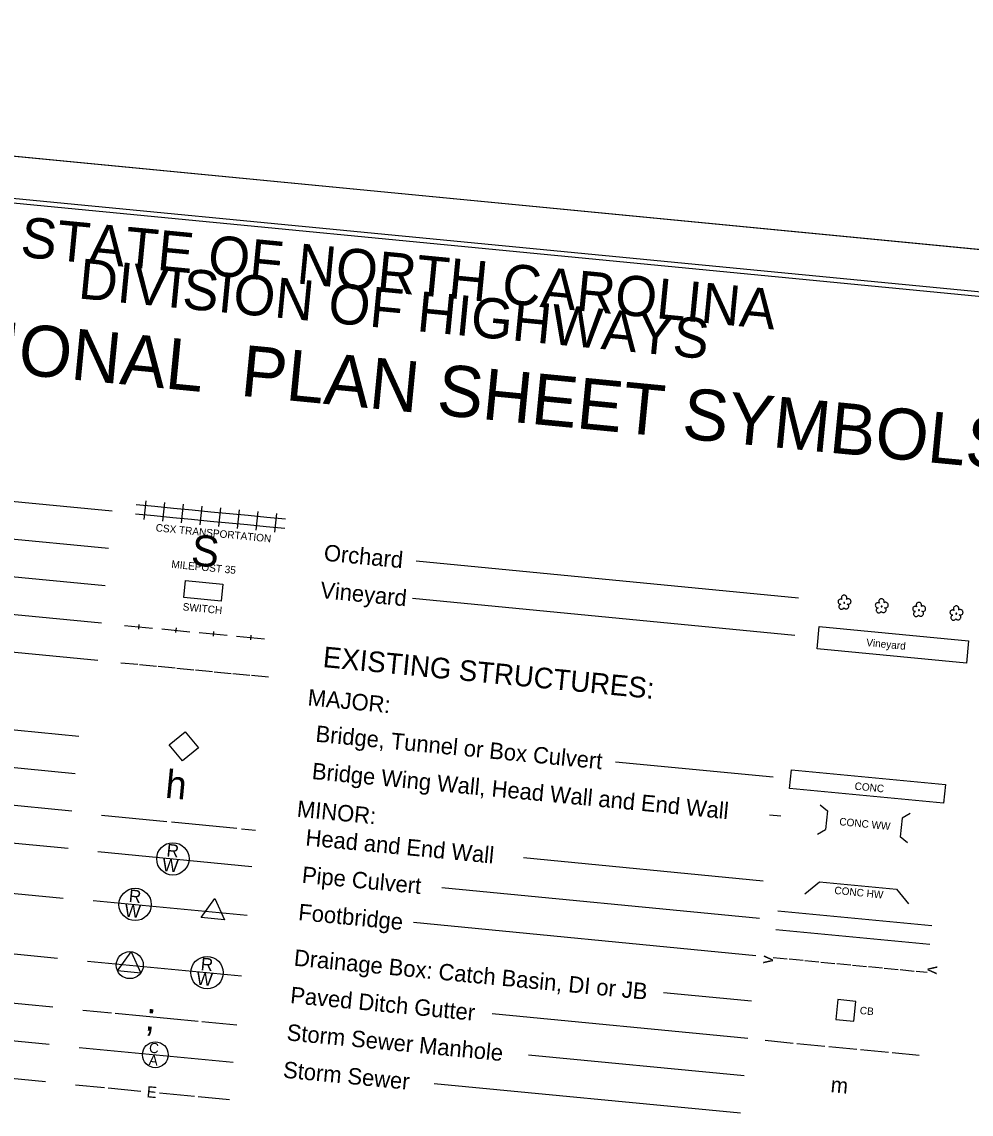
# Model space of a CAD drawing. Extents: x 2060574 to 2063008, y 912203 to 913082.
# Drawn here: x 2062450.1 to 2062753.8, y 912607.4 to 912956.9 of the extents above; entities that cross this region are included whole.
import ezdxf

# ---------------------------------------------------------------- set-up
doc = ezdxf.new("R2010")
doc.units = 0
for name, color, linetype in [('Sheet Cutting Line CELL', 7, 'Continuous'), ('Sheet Data Field CELL', 7, 'Continuous'), ('Sheet Plot Border Inside CELL', 7, 'Continuous'), ('Sheet Plot Border Outside CELL', 7, 'Continuous'), ('Sheet Symbology CELL', 7, 'Continuous')]:
    doc.layers.add(name, color=color, linetype=linetype)

msp = doc.modelspace()

# ---------------------------------------------------------------- linework, layer by layer
at = {"layer": 'Sheet Cutting Line CELL'}
msp.add_line((2063008.23, 912859.64), (2062002.51, 912956.86), dxfattribs=at)
at = {"layer": 'Sheet Data Field CELL'}
msp.add_lwpolyline([(2062497.24, 912725.52), (2062502.37, 912729.74), (2062506.59, 912724.62), (2062501.46, 912720.39)], close=True, dxfattribs=at)
at = {"layer": 'Sheet Plot Border Inside CELL'}
msp.add_lwpolyline([(2061948.07, 912312.58), (2062943.33, 912216.37), (2063004.24, 912846.49), (2062008.98, 912942.7)], close=True, dxfattribs=at)
at = {"layer": 'Sheet Plot Border Outside CELL'}
msp.add_lwpolyline([(2061939.01, 912299.92), (2062944.72, 912202.7), (2063008.23, 912859.64), (2062002.51, 912956.86)], close=True, dxfattribs=at)
at = {"layer": 'Sheet Symbology CELL'}
for p, q in [((2062479.03, 912800.31), (2062384.42, 912809.46)), ((2062486.7, 912802.44), (2062492.67, 912801.86)), ((2062489.26, 912797.67), (2062489.83, 912803.65)), ((2062495.23, 912797.1), (2062495.8, 912803.07)), ((2062501.2, 912796.52), (2062501.78, 912802.49)), ((2062486.41, 912799.45), (2062492.39, 912798.88)), ((2062492.39, 912798.88), (2062498.36, 912798.3)), ((2062492.67, 912801.86), (2062498.65, 912801.29)), ((2062498.65, 912801.29), (2062504.62, 912800.71)), ((2062504.62, 912800.71), (2062510.59, 912800.13)), ((2062507.17, 912795.94), (2062507.75, 912801.91)), ((2062510.59, 912800.13), (2062516.56, 912799.55)), ((2062513.14, 912795.36), (2062513.72, 912801.34)), ((2062516.56, 912799.55), (2062522.54, 912798.98)), ((2062519.12, 912794.79), (2062519.69, 912800.76)), ((2062522.54, 912798.98), (2062528.51, 912798.4)), ((2062525.09, 912794.21), (2062525.67, 912800.18)), ((2062531.06, 912793.63), (2062531.64, 912799.6)), ((2062477.87, 912788.37), (2062388.56, 912797)), ((2062498.36, 912798.3), (2062504.33, 912797.72)), ((2062504.33, 912797.72), (2062510.3, 912797.15)), ((2062510.3, 912797.15), (2062516.27, 912796.57)), ((2062516.27, 912796.57), (2062522.25, 912795.99)), ((2062522.25, 912795.99), (2062528.22, 912795.41)), ((2062528.22, 912795.41), (2062534.19, 912794.84)), ((2062528.51, 912798.4), (2062534.48, 912797.82)), ((2062476.72, 912776.42), (2062348.37, 912788.83)), ((2062698.6, 912772.5), (2062576.21, 912784.33)), ((2062475.56, 912764.48), (2062376.33, 912774.07)), ((2062697.45, 912760.55), (2062575.06, 912772.38)), ((2062482.96, 912763.76), (2062491.92, 912762.9)), ((2062487.51, 912764.08), (2062487.37, 912762.58)), ((2062474.41, 912752.53), (2062375.17, 912762.13)), ((2062474.41, 912752.53), (2062375.17, 912762.13)), ((2062494.91, 912762.61), (2062503.87, 912761.74)), ((2062499.46, 912762.92), (2062499.31, 912761.43)), ((2062506.85, 912761.45), (2062515.81, 912760.59)), ((2062511.4, 912761.77), (2062511.26, 912760.28)), ((2062518.8, 912760.3), (2062527.75, 912759.43)), ((2062523.35, 912760.61), (2062523.2, 912759.12)), ((2062481.81, 912751.82), (2062487.18, 912751.3)), ((2062487.78, 912751.24), (2062493.16, 912750.72)), ((2062493.75, 912750.66), (2062499.13, 912750.15)), ((2062499.73, 912750.09), (2062505.1, 912749.57)), ((2062505.7, 912749.51), (2062511.07, 912748.99)), ((2062511.67, 912748.93), (2062517.04, 912748.41)), ((2062517.64, 912748.36), (2062523.02, 912747.84)), ((2062523.61, 912747.78), (2062528.99, 912747.26)), ((2062468.36, 912728.19), (2062400.15, 912734.79)), ((2062467.2, 912716.25), (2062416.47, 912721.15)), ((2062690.46, 912715.14), (2062640.04, 912720.01)), ((2062466.05, 912704.31), (2062415.32, 912709.21)), ((2062705.55, 912706.36), (2062707.84, 912704.42)), ((2062707.84, 912704.42), (2062707.26, 912698.44)), ((2062475.59, 912703.04), (2062496.49, 912701.02)), ((2062497.98, 912700.87), (2062518.88, 912698.85)), ((2062689.3, 912703.19), (2062692.88, 912702.85)), ((2062731.72, 912702.11), (2062731.15, 912696.13)), ((2062734.34, 912703.58), (2062731.72, 912702.11)), ((2062520.38, 912698.71), (2062524.86, 912698.27)), ((2062704.64, 912696.97), (2062707.26, 912698.44)), ((2062464.89, 912692.36), (2062414.17, 912697.26)), ((2062733.43, 912694.19), (2062731.15, 912696.13)), ((2062474.46, 912691.36), (2062523.73, 912686.6)), ((2062687.25, 912681.95), (2062610.63, 912689.36)), ((2062463.34, 912676.33), (2062423.26, 912680.2)), ((2062700.63, 912677.9), (2062705.26, 912681.72)), ((2062705.26, 912681.72), (2062729.9, 912679.33)), ((2062686.09, 912670.01), (2062584.45, 912679.83)), ((2062729.9, 912679.33), (2062733.72, 912674.7)), ((2062472.95, 912675.76), (2062522.22, 912671)), ((2062511.44, 912672.04), (2062511.44, 912672.04)), ((2062691.94, 912672.46), (2062741.21, 912667.69)), ((2062684.94, 912658.06), (2062575.36, 912668.65)), ((2062691.36, 912666.48), (2062740.63, 912661.72)), ((2062461.49, 912657.19), (2062421.41, 912661.07)), ((2062471.07, 912656.35), (2062520.34, 912651.59)), ((2062690.49, 912657.52), (2062694.97, 912657.09)), ((2062695.57, 912657.03), (2062700.05, 912656.6)), ((2062700.65, 912656.54), (2062705.12, 912656.11)), ((2062705.72, 912656.05), (2062710.2, 912655.62)), ((2062710.8, 912655.56), (2062715.28, 912655.13)), ((2062484.63, 912655.04), (2062484.63, 912655.04)), ((2062715.87, 912655.07), (2062720.35, 912654.64)), ((2062720.95, 912654.58), (2062725.43, 912654.15)), ((2062726.03, 912654.09), (2062730.51, 912653.66)), ((2062731.1, 912653.6), (2062735.58, 912653.17)), ((2062736.18, 912653.11), (2062739.76, 912652.76)), ((2062459.98, 912641.6), (2062401.73, 912647.23)), ((2062683.53, 912643.47), (2062655.34, 912646.2)), ((2062469.56, 912640.67), (2062478.79, 912639.78)), ((2062479.99, 912639.66), (2062506.51, 912637.1)), ((2062682.37, 912631.53), (2062600.59, 912639.43)), ((2062458.83, 912629.65), (2062400.57, 912635.29)), ((2062507.71, 912636.99), (2062518.83, 912635.91)), ((2062687.93, 912630.99), (2062696.89, 912630.12)), ((2062468.4, 912628.73), (2062517.67, 912623.97)), ((2062698.08, 912630.01), (2062707.04, 912629.14)), ((2062708.23, 912629.03), (2062717.19, 912628.16)), ((2062718.39, 912628.05), (2062727.34, 912627.18)), ((2062681.22, 912619.58), (2062612.14, 912626.26)), ((2062728.54, 912627.06), (2062737.2, 912626.23)), ((2062457.68, 912617.71), (2062399.42, 912623.34)), ((2062680.06, 912607.64), (2062582, 912617.12)), ((2062467.25, 912616.78), (2062476.51, 912615.89)), ((2062477.71, 912615.77), (2062488.16, 912614.76)), ((2062494.13, 912614.19), (2062505.33, 912613.1)), ((2062506.52, 912612.99), (2062516.52, 912612.02))]:
    msp.add_line(p, q, dxfattribs=at)
for points in [[(2062996.63, 912845.69), (2062100.81, 912932.29), (2062040.25, 912305.82), (2062936.07, 912219.22)], [(2062502.44, 912778.13), (2062514.38, 912776.98), (2062513.86, 912771.55), (2062501.91, 912772.7)], [(2062507.5, 912670.25), (2062511.86, 912676.34), (2062514.97, 912669.53)], [(2062480.69, 912653.25), (2062485.05, 912659.34), (2062488.16, 912652.53)], [(2062710.54, 912637.66), (2062716.28, 912637.1), (2062716.89, 912643.46), (2062711.15, 912644.01)]]:
    msp.add_lwpolyline(points, close=True, dxfattribs=at)
for points in [[(2062713.9, 912772.07), (2062714, 912772.25), (2062714.05, 912772.42), (2062714.04, 912772.6), (2062714.03, 912772.79), (2062713.95, 912772.94), (2062713.88, 912773.1), (2062713.74, 912773.24), (2062713.6, 912773.34), (2062713.4, 912773.42), (2062713.25, 912773.43), (2062713.06, 912773.42), (2062712.88, 912773.38), (2062712.72, 912773.3), (2062712.56, 912773.2), (2062712.45, 912773.03), (2062712.38, 912772.88), (2062712.33, 912772.71), (2062712.31, 912772.53), (2062712.33, 912772.35), (2062712.4, 912772.19), (2062712.5, 912772), (2062712.36, 912772.1), (2062712.19, 912772.15), (2062712.01, 912772.17), (2062711.85, 912772.12), (2062711.7, 912772.08), (2062711.54, 912771.97), (2062711.41, 912771.86), (2062711.3, 912771.72), (2062711.26, 912771.58), (2062711.21, 912771.37), (2062711.22, 912771.22), (2062711.27, 912771.06), (2062711.37, 912770.9), (2062711.45, 912770.77), (2062711.59, 912770.67), (2062711.76, 912770.56), (2062711.91, 912770.52), (2062712.09, 912770.5), (2062711.93, 912770.46), (2062711.77, 912770.35), (2062711.67, 912770.24), (2062711.59, 912770.07), (2062711.52, 912769.89), (2062711.5, 912769.74), (2062711.52, 912769.56), (2062711.59, 912769.4), (2062711.67, 912769.25), (2062711.77, 912769.12), (2062711.91, 912769.01), (2062712.06, 912768.94), (2062712.24, 912768.92), (2062712.42, 912768.9), (2062712.57, 912768.92), (2062712.73, 912769.02), (2062712.89, 912769.1), (2062713.06, 912769.35)], [(2062713.06, 912769.35), (2062713.4, 912769.11), (2062713.57, 912769.03), (2062713.75, 912768.98), (2062713.93, 912769), (2062714.09, 912769.04), (2062714.25, 912769.12), (2062714.41, 912769.22), (2062714.51, 912769.36), (2062714.58, 912769.51), (2062714.66, 912769.68), (2062714.65, 912769.86), (2062714.64, 912770.04), (2062714.53, 912770.23), (2062714.46, 912770.36), (2062714.32, 912770.47), (2062714.14, 912770.57), (2062714.32, 912770.53), (2062714.53, 912770.51), (2062714.69, 912770.55), (2062714.87, 912770.62), (2062715.03, 912770.7), (2062715.16, 912770.84), (2062715.27, 912771.01), (2062715.32, 912771.18), (2062715.37, 912771.36), (2062715.35, 912771.54), (2062715.31, 912771.73), (2062715.21, 912771.89), (2062715.07, 912772.05), (2062714.93, 912772.16), (2062714.76, 912772.23), (2062714.58, 912772.28), (2062714.4, 912772.3), (2062714.22, 912772.25), (2062714.06, 912772.18), (2062713.9, 912772.07)], [(2062713.29, 912771.08), (2062713.2, 912771.09), (2062713.14, 912771.06), (2062713.07, 912771.04), (2062713.07, 912770.95), (2062713.06, 912770.89), (2062713.11, 912770.82), (2062713.2, 912770.82), (2062713.26, 912770.81), (2062713.33, 912770.86), (2062713.37, 912770.95), (2062713.34, 912771.01), (2062713.29, 912771.08)], [(2062725.84, 912770.92), (2062725.95, 912771.09), (2062726, 912771.27), (2062725.98, 912771.45), (2062725.97, 912771.63), (2062725.9, 912771.79), (2062725.82, 912771.95), (2062725.68, 912772.08), (2062725.54, 912772.18), (2062725.34, 912772.26), (2062725.19, 912772.28), (2062725.01, 912772.27), (2062724.82, 912772.22), (2062724.67, 912772.15), (2062724.5, 912772.04), (2062724.4, 912771.87), (2062724.32, 912771.73), (2062724.28, 912771.55), (2062724.26, 912771.37), (2062724.27, 912771.19), (2062724.35, 912771.03), (2062724.45, 912770.84), (2062724.31, 912770.95), (2062724.13, 912771), (2062723.95, 912771.01), (2062723.8, 912770.97), (2062723.64, 912770.92), (2062723.48, 912770.82), (2062723.35, 912770.71), (2062723.25, 912770.57), (2062723.2, 912770.42), (2062723.15, 912770.22), (2062723.17, 912770.06), (2062723.21, 912769.91), (2062723.32, 912769.75), (2062723.4, 912769.62), (2062723.54, 912769.52), (2062723.71, 912769.41), (2062723.85, 912769.36), (2062724.03, 912769.35), (2062723.88, 912769.3), (2062723.72, 912769.2), (2062723.62, 912769.09), (2062723.54, 912768.91), (2062723.46, 912768.74), (2062723.45, 912768.59), (2062723.46, 912768.41), (2062723.53, 912768.25), (2062723.61, 912768.09), (2062723.72, 912767.96), (2062723.86, 912767.86), (2062724, 912767.78), (2062724.18, 912767.77), (2062724.36, 912767.75), (2062724.51, 912767.76), (2062724.67, 912767.87), (2062724.83, 912767.94), (2062725.01, 912768.2)], [(2062725.01, 912768.2), (2062725.34, 912767.95), (2062725.52, 912767.88), (2062725.69, 912767.83), (2062725.88, 912767.84), (2062726.03, 912767.89), (2062726.19, 912767.96), (2062726.35, 912768.07), (2062726.45, 912768.21), (2062726.53, 912768.35), (2062726.61, 912768.53), (2062726.59, 912768.71), (2062726.58, 912768.89), (2062726.48, 912769.08), (2062726.4, 912769.21), (2062726.26, 912769.31), (2062726.09, 912769.42), (2062726.27, 912769.37), (2062726.47, 912769.35), (2062726.63, 912769.4), (2062726.82, 912769.47), (2062726.98, 912769.54), (2062727.11, 912769.68), (2062727.22, 912769.85), (2062727.26, 912770.03), (2062727.31, 912770.21), (2062727.3, 912770.39), (2062727.26, 912770.57), (2062727.15, 912770.73), (2062727.02, 912770.9), (2062726.87, 912771), (2062726.7, 912771.08), (2062726.53, 912771.13), (2062726.35, 912771.14), (2062726.16, 912771.1), (2062726, 912771.03), (2062725.84, 912770.92)], [(2062737.79, 912769.77), (2062737.89, 912769.94), (2062737.94, 912770.11), (2062737.93, 912770.29), (2062737.92, 912770.48), (2062737.84, 912770.63), (2062737.77, 912770.79), (2062737.63, 912770.93), (2062737.49, 912771.03), (2062737.28, 912771.11), (2062737.13, 912771.12), (2062736.95, 912771.11), (2062736.77, 912771.07), (2062736.61, 912770.99), (2062736.45, 912770.89), (2062736.34, 912770.72), (2062736.27, 912770.58), (2062736.22, 912770.4), (2062736.2, 912770.22), (2062736.22, 912770.04), (2062736.29, 912769.88), (2062736.39, 912769.69), (2062736.25, 912769.79), (2062736.08, 912769.84), (2062735.9, 912769.86), (2062735.74, 912769.81), (2062735.59, 912769.77), (2062735.43, 912769.66), (2062735.29, 912769.55), (2062735.19, 912769.41), (2062735.15, 912769.27), (2062735.1, 912769.06), (2062735.11, 912768.91), (2062735.16, 912768.75), (2062735.26, 912768.59), (2062735.34, 912768.46), (2062735.48, 912768.36), (2062735.65, 912768.25), (2062735.8, 912768.21), (2062735.98, 912768.19), (2062735.82, 912768.15), (2062735.66, 912768.04), (2062735.56, 912767.93), (2062735.48, 912767.76), (2062735.41, 912767.58), (2062735.39, 912767.44), (2062735.4, 912767.25), (2062735.48, 912767.1), (2062735.55, 912766.94), (2062735.66, 912766.81), (2062735.8, 912766.7), (2062735.95, 912766.63), (2062736.13, 912766.61), (2062736.3, 912766.59), (2062736.46, 912766.61), (2062736.62, 912766.71), (2062736.78, 912766.79), (2062736.95, 912767.04)], [(2062725.23, 912769.92), (2062725.14, 912769.93), (2062725.08, 912769.91), (2062725.02, 912769.88), (2062725.01, 912769.79), (2062725, 912769.74), (2062725.06, 912769.67), (2062725.15, 912769.66), (2062725.21, 912769.66), (2062725.27, 912769.71), (2062725.31, 912769.8), (2062725.29, 912769.86), (2062725.23, 912769.92)], [(2062736.95, 912767.04), (2062737.29, 912766.8), (2062737.46, 912766.72), (2062737.64, 912766.68), (2062737.82, 912766.69), (2062737.98, 912766.73), (2062738.13, 912766.81), (2062738.29, 912766.91), (2062738.4, 912767.05), (2062738.47, 912767.2), (2062738.55, 912767.37), (2062738.54, 912767.55), (2062738.52, 912767.74), (2062738.42, 912767.93), (2062738.34, 912768.05), (2062738.2, 912768.16), (2062738.03, 912768.26), (2062738.21, 912768.22), (2062738.42, 912768.2), (2062738.57, 912768.24), (2062738.76, 912768.31), (2062738.92, 912768.39), (2062739.05, 912768.53), (2062739.16, 912768.7), (2062739.21, 912768.87), (2062739.25, 912769.05), (2062739.24, 912769.23), (2062739.2, 912769.42), (2062739.09, 912769.58), (2062738.96, 912769.74), (2062738.82, 912769.85), (2062738.65, 912769.92), (2062738.47, 912769.97), (2062738.29, 912769.99), (2062738.11, 912769.95), (2062737.95, 912769.87), (2062737.79, 912769.77)], [(2062737.18, 912768.77), (2062737.09, 912768.78), (2062737.03, 912768.75), (2062736.96, 912768.73), (2062736.95, 912768.64), (2062736.95, 912768.58), (2062737, 912768.52), (2062737.09, 912768.51), (2062737.15, 912768.5), (2062737.22, 912768.55), (2062737.26, 912768.64), (2062737.23, 912768.7), (2062737.18, 912768.77)], [(2062749.73, 912768.61), (2062749.84, 912768.78), (2062749.89, 912768.96), (2062749.87, 912769.14), (2062749.86, 912769.32), (2062749.78, 912769.48), (2062749.71, 912769.64), (2062749.57, 912769.77), (2062749.43, 912769.88), (2062749.23, 912769.96), (2062749.08, 912769.97), (2062748.9, 912769.96), (2062748.71, 912769.92), (2062748.55, 912769.84), (2062748.39, 912769.73), (2062748.29, 912769.56), (2062748.21, 912769.42), (2062748.16, 912769.24), (2062748.15, 912769.07), (2062748.16, 912768.88), (2062748.24, 912768.73), (2062748.34, 912768.53), (2062748.2, 912768.64), (2062748.02, 912768.69), (2062747.84, 912768.7), (2062747.69, 912768.66), (2062747.53, 912768.61), (2062747.37, 912768.51), (2062747.24, 912768.4), (2062747.14, 912768.26), (2062747.09, 912768.11), (2062747.04, 912767.91), (2062747.06, 912767.75), (2062747.1, 912767.6), (2062747.21, 912767.44), (2062747.28, 912767.31), (2062747.43, 912767.21), (2062747.6, 912767.1), (2062747.74, 912767.06), (2062747.92, 912767.04), (2062747.77, 912766.99), (2062747.61, 912766.89), (2062747.5, 912766.78), (2062747.43, 912766.6), (2062747.35, 912766.43), (2062747.34, 912766.28), (2062747.35, 912766.1), (2062747.42, 912765.94), (2062747.5, 912765.78), (2062747.61, 912765.65), (2062747.75, 912765.55), (2062747.89, 912765.47), (2062748.07, 912765.46), (2062748.25, 912765.44), (2062748.4, 912765.45), (2062748.56, 912765.56), (2062748.72, 912765.63), (2062748.9, 912765.89)], [(2062749.12, 912767.61), (2062749.03, 912767.62), (2062748.97, 912767.6), (2062748.91, 912767.58), (2062748.9, 912767.49), (2062748.89, 912767.43), (2062748.95, 912767.36), (2062749.04, 912767.35), (2062749.1, 912767.35), (2062749.16, 912767.4), (2062749.2, 912767.49), (2062749.18, 912767.55), (2062749.12, 912767.61)], [(2062748.9, 912765.89), (2062749.23, 912765.65), (2062749.41, 912765.57), (2062749.58, 912765.52), (2062749.77, 912765.53), (2062749.92, 912765.58), (2062750.08, 912765.65), (2062750.24, 912765.76), (2062750.34, 912765.9), (2062750.42, 912766.04), (2062750.49, 912766.22), (2062750.48, 912766.4), (2062750.47, 912766.58), (2062750.37, 912766.77), (2062750.29, 912766.9), (2062750.15, 912767), (2062749.98, 912767.11), (2062750.15, 912767.06), (2062750.36, 912767.04), (2062750.52, 912767.09), (2062750.71, 912767.16), (2062750.86, 912767.24), (2062751, 912767.37), (2062751.1, 912767.54), (2062751.15, 912767.72), (2062751.2, 912767.9), (2062751.19, 912768.08), (2062751.14, 912768.26), (2062751.04, 912768.42), (2062750.9, 912768.59), (2062750.76, 912768.69), (2062750.59, 912768.77), (2062750.41, 912768.82), (2062750.23, 912768.83), (2062750.05, 912768.79), (2062749.89, 912768.72), (2062749.73, 912768.61)], [(2062705.2, 912763.42), (2062752.97, 912758.8), (2062752.28, 912751.64), (2062704.5, 912756.26), (2062705.2, 912763.42)], [(2062696.3, 912717.59), (2062745.57, 912712.82), (2062744.99, 912706.85), (2062695.72, 912711.61), (2062696.3, 912717.59)]]:
    msp.add_lwpolyline(points, dxfattribs=at)
for centre, radius in [((2062498.42, 912689.05), 5.17), ((2062486.34, 912674.46), 5.17), ((2062484.63, 912655.04), 4.32), ((2062509.35, 912652.65), 5.17), ((2062492.81, 912626.37), 4.13)]:
    msp.add_circle(centre, radius, dxfattribs=at)

# ---------------------------------------------------------------- texts
for s, height, rotation, p in [('STATE OF NORTH CAROLINA', 12.8514, 354.4787, (2062449.34, 912881.74)), ('DIVISION OF HIGHWAYS', 12.8514, 354.4787, (2062467.85, 912868.4)), ('CONVENTIONAL  PLAN SHEET SYMBOLS', 16.3202, 354.4787, (2062336.25, 912855)), ('CSX TRANSPORTATION', 2.4, 354.4787, (2062492.84, 912793.87)), ('S', 9.9, 354.4787, (2062503.97, 912783.06)), ('Orchard', 5.25, 354.4787, (2062546.55, 912784.47)), ('MILEPOST 35', 2.4, 354.4787, (2062497.86, 912782.19)), ('Vineyard', 5.25, 354.4787, (2062545.4, 912772.52)), ('SWITCH', 2.4, 354.4787, (2062501.48, 912768.57)), ('EXISTING STRUCTURES:', 6.6, 354.4787, (2062546.21, 912750.45)), ('Vineyard', 2.4, 354.4787, (2062720.16, 912757.15)), ('MAJOR:', 5.25, 354.4787, (2062541.39, 912738.19)), ('Bridge, Tunnel or Box Culvert', 5.25, 354.4787, (2062543.9, 912726.56)), ('Bridge Wing Wall, Head Wall and End Wall', 5.25, 354.4787, (2062542.74, 912714.62)), ('h', 9, 354.4787, (2062495.73, 912708.63)), ('CONC', 2.4, 354.4787, (2062716.44, 912711.2)), ('MINOR:', 5.25, 354.4787, (2062537.94, 912702.54)), ('CONC WW', 2.4, 354.4787, (2062711.54, 912699.84)), ('Head and End Wall', 5.25, 354.4787, (2062540.69, 912693.37)), ('R', 4.05, 354.4787, (2062496.26, 912689.86)), ('W', 4.05, 354.4787, (2062494.89, 912685.2)), ('Pipe Culvert', 5.25, 354.4787, (2062539.54, 912681.44)), ('CONC HW', 2.4, 354.4787, (2062709.97, 912677.85)), ('R', 4.05, 354.4787, (2062484.18, 912675.28)), ('W', 4.05, 354.4787, (2062482.81, 912670.62)), ('Footbridge', 5.25, 354.4787, (2062538.39, 912669.49)), ('Drainage Box: Catch Basin, DI or JB', 5.25, 354.4787, (2062536.98, 912654.9)), ('R', 4.05, 354.4787, (2062507.2, 912653.47)), ('v', 3.96, 84.2378, (2062690.27, 912655.29)), ('W', 4.05, 354.4787, (2062505.82, 912648.81)), ('v', 3.96, 264.7196, (2062739.97, 912654.99)), ('Paved Ditch Gutter', 5.25, 354.4787, (2062535.82, 912642.95)), ('CB', 2.4, 354.4787, (2062718.09, 912639.42)), (';', 9, 354.4787, (2062489.28, 912634.24)), ('Storm Sewer Manhole', 5.25, 354.4787, (2062534.67, 912631.01)), ('C', 3.24, 354.4787, (2062490.67, 912627.07)), ('A', 3.24, 354.4787, (2062490.62, 912623.16)), ('Storm Sewer', 5.25, 354.4787, (2062533.51, 912619.06)), ('m', 4.95, 354.4787, (2062708.71, 912614.44)), ('E', 3.6, 354.4787, (2062489.9, 912612.79))]:
    msp.add_text(s, height=height, rotation=rotation, dxfattribs=at).set_placement(p)

doc.saveas('drawing.dxf')
